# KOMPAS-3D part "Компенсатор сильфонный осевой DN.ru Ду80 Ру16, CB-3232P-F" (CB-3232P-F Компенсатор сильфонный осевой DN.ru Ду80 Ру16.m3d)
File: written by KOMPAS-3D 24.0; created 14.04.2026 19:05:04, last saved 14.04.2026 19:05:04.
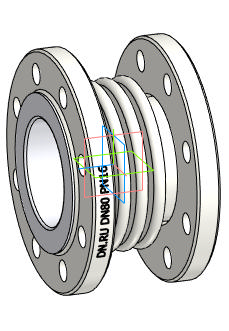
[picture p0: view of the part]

Document properties: Автор: DN.RU; Полное имя файла: D:\PROJECT CAD\DN.RU\..199(ACTUALE). CB-3232P-F Компенсатор сильфонный осевой DN.ru\Исходники\DN80\CB-3232P-F Компенсатор сильфонный осевой DN.ru Ду80 Ру16.m3d

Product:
- Body: Твердое тело1  | qty 1
    Масса: 8.995545
- Part/product: Компенсатор сильфонный осевой DN.ru Ду80 Ру16  | designation CB-3232P-F
    Масса: 6.9
    Раздел спецификации: Прочие изделия
    Комментарий: D140-02140
    Примечание: D140-02140
    additional columns: Типовые

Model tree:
1. Твердое тело1  (labels: Твердое тело1)

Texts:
  CB-3232P-F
